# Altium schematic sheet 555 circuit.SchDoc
size 289 x 210 mm
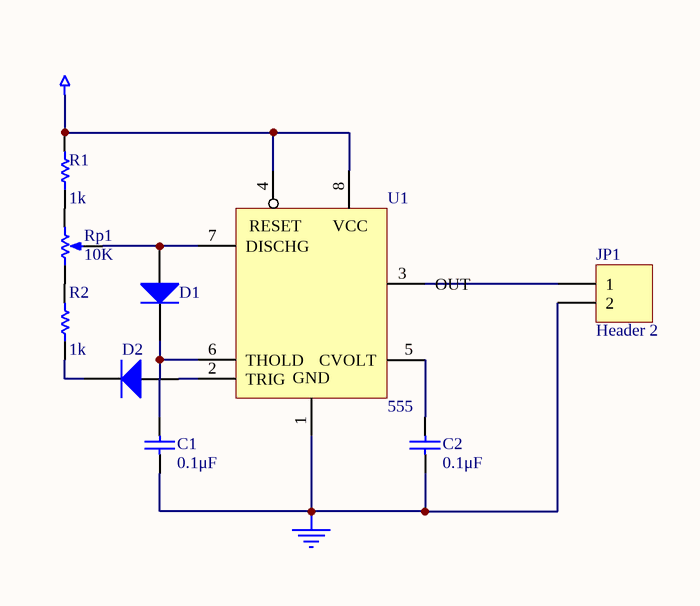
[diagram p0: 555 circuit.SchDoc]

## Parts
C1  0.1μF  [RAD-0.3]
C2  0.1μF  [RAD-0.3]
D1  (no value)  [DSO-C2/X3.3]
D2  (no value)  [DSO-C2/X3.3]
JP1  Header 2  [HDR1X2]
R1  1k  [AXIAL-0.5]
R2  1k  [AXIAL-0.5]
Rp1  value 10K  [VR5]
U1  555

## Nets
GND: C1.1 C2.1 JP1.2 U1.1(GND)
VCC: R1.2 U1.4(RESET) U1.8(VCC)
NetC1_2: C1.2 D1.2(K) U1.6(THOLD)
NetC2_2: C2.2 U1.5(CVOLT)
NetD1_1: D1.1(A) Rp1.3(TAP) U1.7(DISCHG)
NetD2_1: D2.1(A) U1.2(TRIG)
NetD2_2: D2.2(K) R2.1
NetR1_1: R1.1 Rp1.2(BOT)
NetR2_2: R2.2 Rp1.1(TOP)

Not connected (* = marked no-connect by the designer): JP1 1; U1 3(OUT)

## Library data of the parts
C1 C2 = Cap: Capacitor; Manufacturer: Generic Components; Class I: Passive
D1 D2 = Diode: Default Diode; Manufacturer: Generic Components; Class I: Discrete; Class II: Diode - Switching
JP1 = Header 2: Header, 2-Pin; Manufacturer: Generic Components; Class I: Connector
R1 R2 = Res Semi: Semiconductor Resistor; Manufacturer: Generic Components; Class I: Passive
Rp1 = RPot1: Potentiometer; Manufacturer: Generic Components; Class I: Passive; Set Position: 0.5
U1 = 555: Timer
